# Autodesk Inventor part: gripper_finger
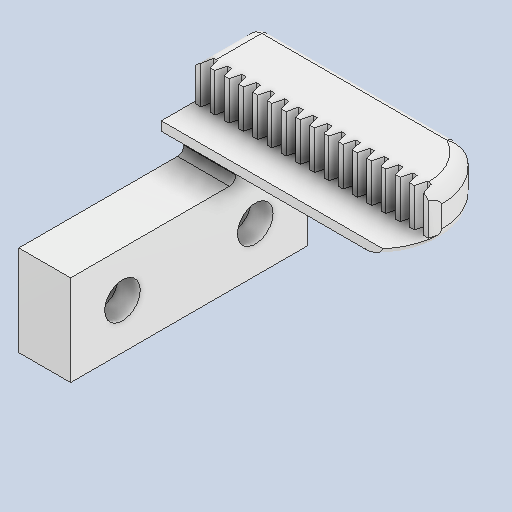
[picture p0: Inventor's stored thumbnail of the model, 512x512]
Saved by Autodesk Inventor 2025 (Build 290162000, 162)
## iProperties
Created: 2025-06
Part Number: gripper_finger
Material: Plastica ABS
Document SubType Name: Modeling
Designer: Ryzen5700u
Density: 1.06 g/cm^3
Appearance: Default
Author: Ryzen5700u
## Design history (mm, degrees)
feature "Solido1"
node "Solido2"
